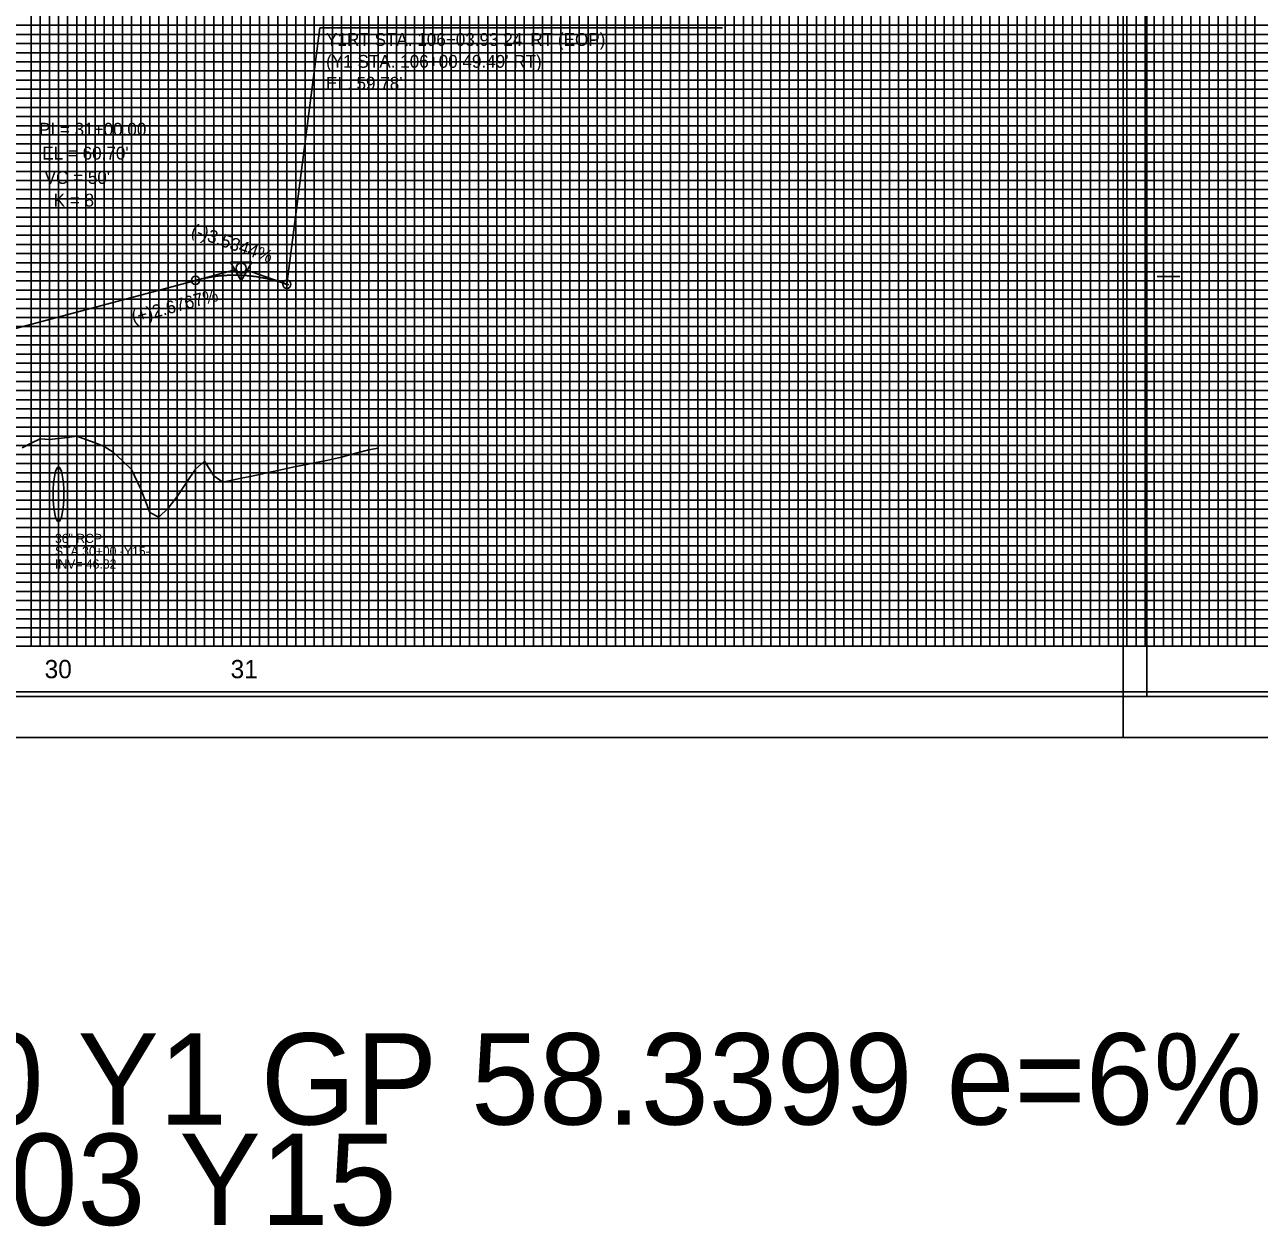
# Model space of a CAD drawing. Extents: x 2345490 to 2436403, y 465165 to 573888.
# Drawn here: x 2383748 to 2384424, y 523226 to 523883 of the extents above; entities that cross this region are included whole.
import ezdxf

# ---------------------------------------------------------------- set-up
doc = ezdxf.new("R2010")
doc.units = 0
for name, color, linetype in [('Old_Level_1', 7, 'Continuous'), ('Old_Level_18', 7, 'Continuous'), ('Old_Level_2', 7, 'Continuous'), ('Old_Level_3', 7, 'Continuous'), ('Old_Level_41', 7, 'Continuous'), ('Old_Level_42', 7, 'Continuous'), ('Old_Level_43', 7, 'Continuous'), ('Old_Level_50', 7, 'Continuous'), ('Old_Level_51', 7, 'Continuous'), ('Old_Level_52', 7, 'Continuous'), ('Old_Level_57', 7, 'Continuous'), ('Old_Level_63', 7, 'Continuous')]:
    doc.layers.add(name, color=color, linetype=linetype)

msp = doc.modelspace()

# ---------------------------------------------------------------- linework, layer by layer
at = {"layer": 'Old_Level_1'}
for points in [[(2383746.799, 523651.7925), (2383751.799, 523654.33725), (2383756.799, 523656.66125), (2383761.799, 523656.42375), (2383766.799, 523656.9995)], [(2383766.799, 523656.9995), (2383771.799, 523657.555), (2383776.799, 523658.11375), (2383781.799, 523656.34725), (2383786.799, 523654.49475), (2383791.799, 523652.59775), (2383796.799, 523649.45675), (2383801.799, 523644.73875), (2383806.799, 523639.975), (2383811.799, 523629.11325), (2383816.799, 523616.4175), (2383821.799, 523613.88975), (2383826.799, 523618.7125), (2383831.799, 523625.2395), (2383836.799, 523632.75975), (2383841.799, 523640.037), (2383846.799, 523644.48475), (2383851.799, 523636.487), (2383856.799, 523632.9965), (2383861.799, 523634.062), (2383866.799, 523635.12725), (2383871.799, 523636.19275), (2383876.799, 523637.25775), (2383881.799, 523638.32075), (2383886.799, 523639.3835), (2383891.799, 523640.4465), (2383896.799, 523641.50525), (2383901.799, 523642.532), (2383906.799, 523643.5585), (2383911.799, 523644.58525), (2383916.799, 523645.612), (2383921.799, 523646.7855), (2383926.799, 523648.12075), (2383931.799, 523649.456), (2383936.799, 523650.79125), (2383941.799, 523651.622)]]:
    msp.add_lwpolyline(points, dxfattribs=at)
at = {"layer": 'Old_Level_18'}
msp.add_lwpolyline([(2384616.79875, 524568.168), (2383116.79875, 524568.168), (2383116.79875, 523518.168), (2384616.79875, 523518.168)], close=True, dxfattribs=at)
at = {"layer": 'Old_Level_2'}
for p, q in [((2383891.799, 523741.33225), (2383909.91425, 523881.85625)), ((2383909.91425, 523881.85625), (2384130.32675, 523881.85625)), ((2383841.799, 523743.4765), (2383864.14275, 523749.457)), ((2383891.799, 523741.33225), (2383869.392, 523749.25175)), ((2383676.799, 523699.3115), (2383841.799, 523743.4765)), ((2383891.799, 523741.33225), (2383892.829, 523740.968))]:
    msp.add_line(p, q, dxfattribs=at)
msp.add_lwpolyline([(2383872.72475, 523753.4525), (2383860.98225, 523753.438), (2383866.86575, 523743.31975)], close=True, dxfattribs=at)
for centre, radius in [((2383866.799, 523750.168), 2.75), ((2383866.799, 523750.168), 2.75), ((2383841.799, 523743.4765), 2.25), ((2383891.799, 523741.33225), 2.25)]:
    msp.add_circle(centre, radius, dxfattribs=at)
msp.add_spline([(2383841.799, 523743.4765), (2383842.799, 523743.738), (2383843.799, 523743.987), (2383844.799, 523744.2235), (2383845.799, 523744.44775), (2383846.799, 523744.6595), (2383847.799, 523744.85875), (2383848.799, 523745.04575), (2383849.799, 523745.22025), (2383850.799, 523745.38225), (2383851.799, 523745.532), (2383852.799, 523745.66925), (2383853.799, 523745.794), (2383854.799, 523745.9065), (2383855.799, 523746.0065), (2383856.799, 523746.094), (2383857.799, 523746.169), (2383858.799, 523746.23175), (2383859.799, 523746.282), (2383860.799, 523746.32), (2383861.799, 523746.34525), (2383862.799, 523746.3585), (2383863.799, 523746.359), (2383864.799, 523746.34725), (2383865.799, 523746.323), (2383866.799, 523746.28625), (2383867.799, 523746.237), (2383868.799, 523746.1755), (2383869.799, 523746.10175), (2383870.799, 523746.01525), (2383871.799, 523745.9165), (2383872.799, 523745.80525), (2383873.799, 523745.68175), (2383874.799, 523745.5455), (2383875.799, 523745.39725), (2383876.799, 523745.23625), (2383877.799, 523745.063), (2383878.799, 523744.87725), (2383879.799, 523744.679), (2383880.799, 523744.4685), (2383881.799, 523744.2455), (2383882.799, 523744.01), (2383883.799, 523743.76225), (2383884.799, 523743.502), (2383885.799, 523743.22925), (2383886.799, 523742.944), (2383887.799, 523742.6465), (2383888.799, 523742.3365), (2383889.799, 523742.01425), (2383890.799, 523741.6795), (2383891.799, 523741.33225)], degree=3, dxfattribs=at)
at = {"layer": 'Old_Level_3'}
msp.add_ellipse((2383766.799, 523626.368), major_axis=(0, 15), ratio=0.194033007, dxfattribs=at)
at = {"layer": 'Old_Level_41'}
for p, q in [((2384368.29875, 523745.668), (2384380.79875, 523745.668)), ((2384616.79875, 523543.168), (2383116.79875, 523543.168))]:
    msp.add_line(p, q, dxfattribs=at)
for points in [[(2383741.79875, 523543.168), (2383791.79875, 523543.168), (2383791.79875, 524568.168)], [(2383766.79875, 524568.168), (2383766.79875, 523543.168), (2383816.79875, 523543.168), (2383816.79875, 524568.168)], [(2383841.79875, 524568.168), (2383841.79875, 523543.168), (2383891.79875, 523543.168), (2383891.79875, 524568.168)], [(2383866.79875, 524568.168), (2383866.79875, 523543.168), (2383916.79875, 523543.168), (2383916.79875, 524568.168)], [(2383941.79875, 524568.168), (2383941.79875, 523543.168), (2383991.79875, 523543.168), (2383991.79875, 524568.168)], [(2383966.79875, 524568.168), (2383966.79875, 523543.168), (2384016.79875, 523543.168), (2384016.79875, 524568.168)], [(2384041.79875, 524568.168), (2384041.79875, 523543.168), (2384091.79875, 523543.168), (2384091.79875, 524568.168)], [(2384066.79875, 524568.168), (2384066.79875, 523543.168), (2384116.79875, 523543.168), (2384116.79875, 524568.168)], [(2384141.79875, 524568.168), (2384141.79875, 523543.168), (2384191.79875, 523543.168), (2384191.79875, 524568.168)], [(2384166.79875, 524568.168), (2384166.79875, 523543.168), (2384216.79875, 523543.168), (2384216.79875, 524568.168)], [(2384241.79875, 524568.168), (2384241.79875, 523543.168), (2384291.79875, 523543.168), (2384291.79875, 524568.168)], [(2384266.79875, 524568.168), (2384266.79875, 523543.168), (2384316.79875, 523543.168), (2384316.79875, 524568.168)], [(2384341.79875, 524568.168), (2384341.79875, 523543.168), (2384391.79875, 523543.168), (2384391.79875, 524568.168)], [(2384366.79875, 524568.168), (2384366.79875, 523543.168), (2384416.79875, 523543.168), (2384416.79875, 524568.168)], [(2384616.79875, 523868.168), (2383116.79875, 523868.168), (2383116.79875, 523818.168), (2384616.79875, 523818.168)], [(2384616.79875, 523793.168), (2383116.79875, 523793.168), (2383116.79875, 523843.168), (2384616.79875, 523843.168)], [(2384616.79875, 523768.168), (2383116.79875, 523768.168), (2383116.79875, 523718.168), (2384616.79875, 523718.168)], [(2384616.79875, 523668.168), (2383116.79875, 523668.168), (2383116.79875, 523618.168), (2384616.79875, 523618.168)], [(2384616.79875, 523593.168), (2383116.79875, 523593.168), (2383116.79875, 523643.168), (2384616.79875, 523643.168)], [(2384616.79875, 523568.168), (2383116.79875, 523568.168)]]:
    msp.add_lwpolyline(points, dxfattribs=at)
at = {"layer": 'Old_Level_42'}
msp.add_lwpolyline([(2384616.79875, 523693.168), (2383116.79875, 523693.168), (2383116.79875, 523743.168), (2384616.79875, 523743.168)], dxfattribs=at)
at = {"layer": 'Old_Level_43'}
for points in [[(2383751.79875, 524568.168), (2383751.79875, 523543.168), (2383756.79875, 523543.168), (2383756.79875, 524568.168)], [(2383761.79875, 524568.168), (2383761.79875, 523543.168), (2383771.79875, 523543.168), (2383771.79875, 524568.168)], [(2383776.79875, 524568.168), (2383776.79875, 523543.168), (2383781.79875, 523543.168), (2383781.79875, 524568.168)], [(2383786.79875, 524568.168), (2383786.79875, 523543.168), (2383796.79875, 523543.168), (2383796.79875, 524568.168)], [(2383801.79875, 524568.168), (2383801.79875, 523543.168), (2383806.79875, 523543.168), (2383806.79875, 524568.168)], [(2383811.79875, 524568.168), (2383811.79875, 523543.168), (2383821.79875, 523543.168), (2383821.79875, 524568.168)], [(2383826.79875, 524568.168), (2383826.79875, 523543.168), (2383831.79875, 523543.168), (2383831.79875, 524568.168)], [(2383836.79875, 524568.168), (2383836.79875, 523543.168), (2383846.79875, 523543.168), (2383846.79875, 524568.168)], [(2383851.79875, 524568.168), (2383851.79875, 523543.168), (2383856.79875, 523543.168), (2383856.79875, 524568.168)], [(2383861.79875, 524568.168), (2383861.79875, 523543.168), (2383871.79875, 523543.168), (2383871.79875, 524568.168)], [(2383876.79875, 524568.168), (2383876.79875, 523543.168)], [(2383876.79875, 523543.168), (2383881.79875, 523543.168), (2383881.79875, 524567.568)], [(2383886.79875, 524567.568), (2383886.79875, 523543.168), (2383896.79875, 523543.168), (2383896.79875, 524568.168)], [(2383901.79875, 524568.168), (2383901.79875, 523543.168), (2383906.79875, 523543.168), (2383906.79875, 524568.168)], [(2383911.79875, 524568.168), (2383911.79875, 523543.168), (2383921.79875, 523543.168), (2383921.79875, 524568.168)], [(2383926.79875, 524568.168), (2383926.79875, 523543.168), (2383931.79875, 523543.168), (2383931.79875, 524568.168)], [(2383936.79875, 524568.168), (2383936.79875, 523543.168), (2383946.79875, 523543.168), (2383946.79875, 524568.168)], [(2383951.79875, 524568.168), (2383951.79875, 523543.168), (2383956.79875, 523543.168), (2383956.79875, 524568.168)], [(2383961.79875, 524568.168), (2383961.79875, 523543.168), (2383971.79875, 523543.168), (2383971.79875, 524568.168)], [(2383976.79875, 524568.168), (2383976.79875, 523543.168), (2383981.79875, 523543.168), (2383981.79875, 524568.168)], [(2383986.79875, 524568.168), (2383986.79875, 523543.168), (2383996.79875, 523543.168), (2383996.79875, 524568.168)], [(2384001.79875, 524568.168), (2384001.79875, 523543.168), (2384006.79875, 523543.168), (2384006.79875, 524568.168)], [(2384011.79875, 524568.168), (2384011.79875, 523543.168), (2384021.79875, 523543.168), (2384021.79875, 524568.168)], [(2384026.79875, 524568.168), (2384026.79875, 523543.168), (2384031.79875, 523543.168), (2384031.79875, 524568.168)], [(2384036.79875, 524568.168), (2384036.79875, 523543.168), (2384046.79875, 523543.168), (2384046.79875, 524568.168)], [(2384051.79875, 524568.168), (2384051.79875, 523543.168), (2384056.79875, 523543.168), (2384056.79875, 524568.168)], [(2384061.79875, 524568.168), (2384061.79875, 523543.168), (2384071.79875, 523543.168), (2384071.79875, 524568.168)], [(2384076.79875, 524568.168), (2384076.79875, 523543.168), (2384081.79875, 523543.168), (2384081.79875, 524568.168)], [(2384086.79875, 524568.168), (2384086.79875, 523543.168), (2384096.79875, 523543.168), (2384096.79875, 524568.168)], [(2384101.79875, 524568.168), (2384101.79875, 523543.168), (2384106.79875, 523543.168), (2384106.79875, 524568.168)], [(2384111.79875, 524568.168), (2384111.79875, 523543.168), (2384121.79875, 523543.168), (2384121.79875, 524568.168)], [(2384126.79875, 524568.168), (2384126.79875, 523543.168), (2384131.79875, 523543.168), (2384131.79875, 524568.168)], [(2384136.79875, 524568.168), (2384136.79875, 523543.168), (2384146.79875, 523543.168), (2384146.79875, 524568.168)], [(2384151.79875, 524568.168), (2384151.79875, 523543.168), (2384156.79875, 523543.168), (2384156.79875, 524568.168)], [(2384161.79875, 524568.168), (2384161.79875, 523543.168), (2384171.79875, 523543.168), (2384171.79875, 524568.168)], [(2384176.79875, 524568.168), (2384176.79875, 523543.168), (2384181.79875, 523543.168), (2384181.79875, 524568.168)], [(2384186.79875, 524568.168), (2384186.79875, 523543.168)], [(2384186.79875, 523543.168), (2384196.79875, 523543.168), (2384196.79875, 524568.168)], [(2384201.79875, 524568.168), (2384201.79875, 523543.168), (2384206.79875, 523543.168), (2384206.79875, 524568.168)], [(2384211.79875, 524568.168), (2384211.79875, 523543.168), (2384221.79875, 523543.168), (2384221.79875, 524568.168)], [(2384226.79875, 524568.168), (2384226.79875, 523543.168), (2384231.79875, 523543.168), (2384231.79875, 524568.168)], [(2384236.79875, 524568.168), (2384236.79875, 523543.168), (2384246.79875, 523543.168), (2384246.79875, 524568.168)], [(2384251.79875, 524568.168), (2384251.79875, 523543.168), (2384256.79875, 523543.168), (2384256.79875, 524568.168)], [(2384261.79875, 524568.168), (2384261.79875, 523543.168), (2384271.79875, 523543.168), (2384271.79875, 524568.168)], [(2384276.79875, 524568.168), (2384276.79875, 523543.168), (2384281.79875, 523543.168), (2384281.79875, 524568.168)], [(2384286.79875, 524568.168), (2384286.79875, 523543.168), (2384296.79875, 523543.168), (2384296.79875, 524568.168)], [(2384301.79875, 524568.168), (2384301.79875, 523543.168), (2384306.79875, 523543.168), (2384306.79875, 524568.168)], [(2384311.79875, 524568.168), (2384311.79875, 523543.168), (2384321.79875, 523543.168), (2384321.79875, 524568.168)], [(2384326.79875, 524568.168), (2384326.79875, 523543.168), (2384331.79875, 523543.168), (2384331.79875, 524568.168)], [(2384336.79875, 524568.168), (2384336.79875, 523543.168), (2384346.79875, 523543.168), (2384346.79875, 524568.168)], [(2384351.79875, 524568.168), (2384351.79875, 523543.168), (2384356.79875, 523543.168), (2384356.79875, 524568.168)], [(2384361.79875, 524568.168), (2384361.79875, 523543.168), (2384371.79875, 523543.168), (2384371.79875, 524568.168)], [(2384376.79875, 524568.168), (2384376.79875, 523543.168), (2384381.79875, 523543.168), (2384381.79875, 524568.168)], [(2384386.79875, 524568.168), (2384386.79875, 523543.168), (2384396.79875, 523543.168), (2384396.79875, 524568.168)], [(2384401.79875, 524568.168), (2384401.79875, 523543.168), (2384406.79875, 523543.168), (2384406.79875, 524568.168)], [(2384411.79875, 524568.168), (2384411.79875, 523543.168), (2384421.79875, 523543.168), (2384421.79875, 524430.618)], [(2384566.79875, 523883.168), (2383166.79875, 523883.168), (2383166.79875, 523878.168), (2384566.79875, 523878.168)], [(2384566.79875, 523873.168), (2383166.79875, 523873.168), (2383166.79875, 523863.168), (2384566.79875, 523863.168)], [(2384566.79875, 523858.168), (2383166.79875, 523858.168), (2383166.79875, 523853.168), (2384566.79875, 523853.168)], [(2384566.79875, 523848.168), (2383166.79875, 523848.168), (2383166.79875, 523838.168), (2384566.79875, 523838.168)], [(2384566.79875, 523833.168), (2383166.79875, 523833.168), (2383166.79875, 523828.168), (2384566.79875, 523828.168)], [(2384566.79875, 523823.168), (2383166.79875, 523823.168), (2383166.79875, 523813.168), (2384566.79875, 523813.168)], [(2384566.79875, 523808.168), (2383166.79875, 523808.168), (2383166.79875, 523803.168), (2384566.79875, 523803.168)], [(2384566.79875, 523798.168), (2383166.79875, 523798.168), (2383166.79875, 523788.168), (2384566.79875, 523788.168)], [(2384566.79875, 523783.168), (2383166.79875, 523783.168), (2383166.79875, 523778.168), (2384566.79875, 523778.168)], [(2384566.79875, 523773.168), (2383166.79875, 523773.168), (2383166.79875, 523763.168), (2384566.79875, 523763.168)], [(2384566.79875, 523758.168), (2383166.79875, 523758.168), (2383166.79875, 523753.168), (2384566.79875, 523753.168)], [(2384566.79875, 523748.168), (2383166.79875, 523748.168)], [(2383166.79875, 523738.168), (2384566.79875, 523738.168)], [(2384566.79875, 523733.168), (2383166.79875, 523733.168), (2383166.79875, 523728.168), (2384566.79875, 523728.168)], [(2384566.79875, 523723.168), (2383166.79875, 523723.168)], [(2383166.79875, 523713.168), (2384566.79875, 523713.168)], [(2384566.79875, 523708.168), (2383166.79875, 523708.168), (2383166.79875, 523703.168), (2384566.79875, 523703.168)], [(2384566.79875, 523698.168), (2383166.79875, 523698.168), (2383166.79875, 523688.168), (2384566.79875, 523688.168)], [(2384566.79875, 523683.168), (2383166.79875, 523683.168), (2383166.79875, 523678.168), (2384566.79875, 523678.168)], [(2384566.79875, 523673.168), (2383166.79875, 523673.168), (2383166.79875, 523663.168), (2384566.79875, 523663.168)], [(2384566.79875, 523658.168), (2383166.79875, 523658.168), (2383166.79875, 523653.168), (2384566.79875, 523653.168)], [(2384566.79875, 523648.168), (2383166.79875, 523648.168), (2383166.79875, 523638.168), (2384566.79875, 523638.168)], [(2384566.79875, 523633.168), (2383166.79875, 523633.168), (2383166.79875, 523628.168), (2384566.79875, 523628.168)], [(2384566.79875, 523623.168), (2383166.79875, 523623.168), (2383166.79875, 523613.168), (2384566.79875, 523613.168)], [(2384566.79875, 523608.168), (2383166.79875, 523608.168), (2383166.79875, 523603.168), (2384566.79875, 523603.168)], [(2384566.79875, 523598.168), (2383166.79875, 523598.168), (2383166.79875, 523588.168), (2384566.79875, 523588.168)], [(2384566.79875, 523583.168), (2383166.79875, 523583.168), (2383166.79875, 523578.168), (2384566.79875, 523578.168)], [(2384566.79875, 523573.168), (2383166.79875, 523573.168), (2383166.79875, 523563.168), (2384566.79875, 523563.168)], [(2384566.79875, 523558.168), (2383166.79875, 523558.168), (2383166.79875, 523553.168), (2384566.79875, 523553.168)], [(2384566.79875, 523548.168), (2383166.79875, 523548.168)]]:
    msp.add_lwpolyline(points, dxfattribs=at)
at = {"layer": 'Old_Level_50'}
msp.add_line((2384349.79875, 523493.168), (2384349.79875, 523493.168), dxfattribs=at)
for points in [[(2384629.29875, 524570.718), (2382962.79875, 524570.718), (2382962.79875, 523515.618), (2384629.29875, 523515.618)], [(2386029.29875, 524570.718), (2384362.79875, 524570.718), (2384362.79875, 523515.618), (2386029.29875, 523515.618)]]:
    msp.add_lwpolyline(points, close=True, dxfattribs=at)
at = {"layer": 'Old_Level_51'}
for points in [[(2384633.79875, 524593.168), (2382949.79875, 524593.168), (2382949.79875, 523493.168), (2384633.79875, 523493.168)], [(2386033.79875, 524593.168), (2384349.79875, 524593.168), (2384349.79875, 523493.168), (2386033.79875, 523493.168)]]:
    msp.add_lwpolyline(points, close=True, dxfattribs=at)
at = {"layer": 'Old_Level_52'}
msp.add_line((2384362.79875, 523515.618), (2384362.79875, 523515.618), dxfattribs=at)
at = {"layer": 'Old_Level_57'}
for p, q in [((2381716.79925, 523843.16825), (2384066.79875, 523843.16825)), ((2383766.79875, 523543.16825), (2383766.79875, 523843.16825)), ((2383766.79875, 523543.26825), (2383766.79875, 523843.16825)), ((2383866.79875, 523543.16825), (2383866.79875, 523843.16825)), ((2383866.79875, 523543.26825), (2383866.79875, 523843.16825)), ((2383966.79875, 523543.16825), (2383966.79875, 523843.16825)), ((2383966.79875, 523543.26825), (2383966.79875, 523843.16825)), ((2384066.79875, 523543.16825), (2384066.79875, 523843.16825)), ((2384066.79875, 523543.26825), (2384066.79875, 523843.16825)), ((2381716.79925, 523793.16825), (2384066.79875, 523793.16825)), ((2381716.79925, 523743.16825), (2384066.79875, 523743.16825)), ((2381716.79925, 523693.16825), (2384066.79875, 523693.16825)), ((2381716.79925, 523643.16825), (2384066.79875, 523643.16825)), ((2381716.799, 523593.16825), (2384066.79875, 523593.16825)), ((2381716.79925, 523543.16825), (2384066.79875, 523543.16825))]:
    msp.add_line(p, q, dxfattribs=at)
at = {"layer": 'Old_Level_63'}
msp.add_line((2381766.79875, 523543.168), (2383942.32375, 523543.168), dxfattribs=at)

# ---------------------------------------------------------------- texts
at = {"layer": 'Old_Level_1'}
for s, height, p in [('30', 10.000001, (2383759.1855, 523525.668)), ('31', 10.000001, (2383861.025, 523525.668)), ("106+00 Y1 GP 58.3399 e=6% 24'", 49.9999995, (2383533.6215, 523281.2865)), ('31+26.03 Y15', 49.9999995, (2383533.6215, 523226.28675))]:
    msp.add_text(s, height=height, dxfattribs=at).set_placement(p)
at = {"layer": 'Old_Level_2'}
for s, height, p in [("Y1RT STA. 106+03.93 24' RT (EOP)", 7.0000005, (2383913.29925, 523871.904)), ("(Y1 STA. 106+00 49.49' RT)", 7.0000005, (2383913.29925, 523859.904)), ("EL. 59.78'", 7.000001, (2383913.29925, 523847.904)), ('PI = 31+00.00', 7.0000005, (2383756.068, 523822.76075)), ("EL = 60.70'", 7.0000005, (2383757.85225, 523809.6625)), ("VC = 50'", 7.000001, (2383759.1685, 523796.3165)), ('K = 8', 7.000001, (2383764.1075, 523783.94025))]:
    msp.add_text(s, height=height, dxfattribs=at).set_placement(p)
for s, rotation, p in [('(-)3.5344%', 340.53463889, (2383838.828, 523768.248)), ('(+)2.6767%', 14.98489444, (2383807.82275, 523719.81625))]:
    msp.add_text(s, height=7.000001, rotation=rotation, dxfattribs=at).set_placement(p)
at = {"layer": 'Old_Level_3'}
for s, height, p in [('36" RCP', 5, (2383764.8555, 523599.72275)), ('STA 30+00 -Y15-', 4.9999995, (2383764.8555, 523592.72275)), ('INV= 46.82', 5, (2383764.8555, 523585.72275))]:
    msp.add_text(s, height=height, dxfattribs=at).set_placement(p)

doc.saveas('drawing.dxf')
